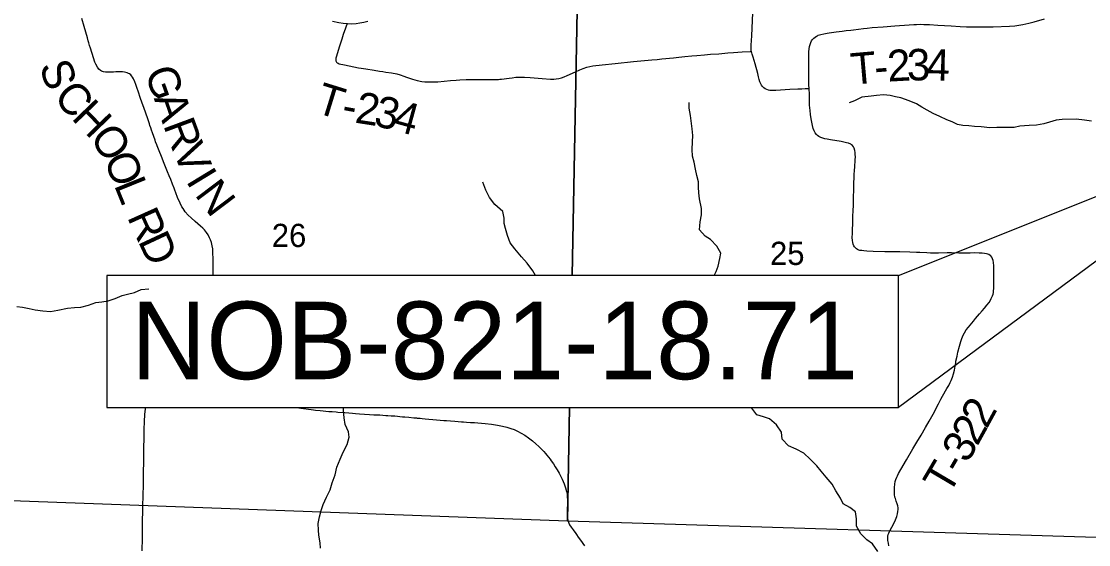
# Model space of a CAD drawing. Extents: x 0 to 34, y 0 to 22.
# Drawn here: x 3.363 to 5.288, y 16.577 to 17.521 of the extents above; entities that cross this region are included whole.
import ezdxf

# ---------------------------------------------------------------- set-up
doc = ezdxf.new("R2010")
doc.units = 0
for name, color, linetype in [('GM_X_Corporation', 7, 'Continuous'), ('GM_X_County_Road', 7, 'Continuous'), ('GM_X_Minor_River', 7, 'Continuous'), ('GM_X_Section_Text', 7, 'Continuous'), ('GM_X_State_Route', 7, 'Continuous'), ('GM_X_Township_Road', 7, 'Continuous'), ('GM_X_Township_Road_Text', 7, 'Continuous'), ('TX_P_1', 7, 'Continuous')]:
    doc.layers.add(name, color=color, linetype=linetype)

msp = doc.modelspace()

# ---------------------------------------------------------------- linework, layer by layer
at = {"layer": 'GM_X_Corporation'}
for points in [[(4.352, 16.8239), (4.3481, 16.6188), (3.3284, 16.656), (3.3465, 17.6805), (4.3675, 17.6365), (4.3565, 17.0622)], [(4.3565, 17.0622), (4.3675, 17.6365), (5.3765, 17.6099), (5.3761, 17.5925), (5.36, 16.5874), (4.3481, 16.6188), (4.352, 16.8239)]]:
    msp.add_lwpolyline(points, dxfattribs=at)
at = {"layer": 'GM_X_County_Road'}
for points in [[(3.5809, 16.5652), (3.5815, 16.5882), (3.5817, 16.6037), (3.5818, 16.6242), (3.5819, 16.6323), (3.5822, 16.6484), (3.5826, 16.6627), (3.5832, 16.6869), (3.5834, 16.7), (3.584, 16.7335), (3.5842, 16.7515), (3.5844, 16.7689), (3.5845, 16.7745), (3.5846, 16.7844), (3.585, 16.7987), (3.5856, 16.8111), (3.5861, 16.8166), (3.5867, 16.8209), (3.5874, 16.8239)], [(3.8591, 16.8239), (3.8674, 16.8227), (3.8859, 16.8204), (3.8902, 16.8199), (3.8933, 16.8195), (3.9019, 16.8186), (3.9179, 16.8171), (3.9234, 16.8166), (3.9309, 16.816), (3.934, 16.8158), (3.9463, 16.8148), (3.9537, 16.8142), (3.9605, 16.8136), (3.9655, 16.8132), (3.9729, 16.8126), (3.9907, 16.8112), (3.9987, 16.8109), (4.0099, 16.8105), (4.0148, 16.8102), (4.0204, 16.8098), (4.0241, 16.8096), (4.0303, 16.8092), (4.0347, 16.8089), (4.0365, 16.8087), (4.0507, 16.8074), (4.055, 16.807), (4.0618, 16.8065), (4.071, 16.8056), (4.0759, 16.8051), (4.0772, 16.805), (4.0809, 16.8047), (4.0821, 16.8046), (4.0858, 16.8043), (4.0914, 16.8038), (4.0982, 16.8032), (4.1055, 16.8025), (4.1251, 16.8008), (4.1299, 16.8004), (4.1373, 16.7998), (4.1447, 16.7993), (4.1509, 16.7989), (4.1571, 16.7984), (4.1608, 16.7982), (4.1657, 16.7978), (4.1732, 16.7972), (4.1806, 16.7967), (4.1862, 16.7963), (4.1998, 16.7952), (4.2109, 16.7939), (4.2219, 16.7922), (4.2311, 16.7905), (4.2389, 16.7885), (4.246, 16.7863), (4.2518, 16.7841), (4.258, 16.7813), (4.2646, 16.7779), (4.271, 16.774), (4.2776, 16.7694), (4.285, 16.7637), (4.2911, 16.7585), (4.2967, 16.7535), (4.3019, 16.7482), (4.3054, 16.7447), (4.3086, 16.7409), (4.311, 16.7381), (4.3166, 16.7307), (4.3187, 16.7277), (4.3226, 16.7223), (4.3261, 16.7172), (4.3297, 16.7114), (4.3331, 16.7055), (4.3356, 16.7005), (4.3383, 16.6949), (4.3419, 16.6863), (4.3447, 16.6788), (4.3464, 16.6723), (4.3473, 16.6674), (4.3477, 16.6631), (4.348, 16.6569), (4.3479, 16.65), (4.3475, 16.6401), (4.3474, 16.6333), (4.3476, 16.6284), (4.3484, 16.6229), (4.3494, 16.6187), (4.3506, 16.6151), (4.3519, 16.6124), (4.3548, 16.6083), (4.3583, 16.6032), (4.363, 16.5967), (4.3644, 16.5947), (4.3676, 16.5902), (4.3716, 16.5846), (4.3788, 16.5746)]]:
    msp.add_lwpolyline(points, dxfattribs=at)
at = {"layer": 'GM_X_Minor_River'}
for points in [[(5.2936, 17.3404), (5.2807, 17.3426), (5.2655, 17.344), (5.2405, 17.3438), (5.2295, 17.3422), (5.2174, 17.3387), (5.2075, 17.3356), (5.1943, 17.3332), (5.1806, 17.3327), (5.1643, 17.3314), (5.1538, 17.3291), (5.1386, 17.329), (5.1227, 17.3292), (5.1098, 17.3287), (5.0946, 17.3305), (5.0825, 17.3308), (5.0718, 17.3322), (5.0612, 17.3329), (5.0517, 17.3347), (5.0418, 17.3392), (5.0323, 17.3429), (5.0198, 17.3489), (5.008, 17.3545), (4.997, 17.3605), (4.9874, 17.3657), (4.9779, 17.3717), (4.9646, 17.3773), (4.9494, 17.3825), (4.9399, 17.3843), (4.93, 17.3869), (4.9179, 17.3883), (4.9058, 17.3867), (4.8956, 17.3858), (4.8793, 17.3838), (4.866, 17.3776), (4.8562, 17.3737)], [(4.6124, 17.0622), (4.6161, 17.0694), (4.6199, 17.0789), (4.6228, 17.093), (4.6246, 17.1025), (4.6173, 17.1149), (4.6063, 17.127), (4.5964, 17.1334), (4.5864, 17.1447), (4.5875, 17.1591), (4.5896, 17.1716), (4.5896, 17.183), (4.5864, 17.2008), (4.5852, 17.2114), (4.5844, 17.2217), (4.5843, 17.2312), (4.5815, 17.2429), (4.5788, 17.2543), (4.5764, 17.2664), (4.5737, 17.2777), (4.5733, 17.2895), (4.5735, 17.3032), (4.5742, 17.3149), (4.573, 17.3267), (4.5718, 17.3365), (4.5698, 17.3509), (4.5674, 17.3638), (4.5673, 17.3741)], [(4.2649, 17.0958), (4.2534, 17.1101), (4.2446, 17.1214), (4.24, 17.1343), (4.2361, 17.1468), (4.2341, 17.1562), (4.2341, 17.1657), (4.2313, 17.1775), (4.2168, 17.1903), (4.2073, 17.2031), (4.2011, 17.2163), (4.1957, 17.2303)], [(4.2902, 17.0622), (4.2856, 17.0705), (4.2752, 17.0845), (4.2649, 17.0958)], [(3.3549, 17.0065), (3.3648, 17.0051), (3.3773, 17.0025), (3.388, 17.0003), (3.402, 16.9982), (3.4157, 16.9971), (3.4289, 16.9995), (3.4463, 17.0031), (3.4588, 17.0043), (3.4702, 17.0052), (3.4842, 17.0087), (3.4974, 17.0137), (3.508, 17.0146), (3.5194, 17.0162), (3.5323, 17.0205), (3.5447, 17.0259), (3.5546, 17.0286), (3.5671, 17.0317), (3.5792, 17.0371), (3.5928, 17.038)], [(3.9199, 16.6752), (3.9236, 16.6882), (3.9288, 16.7026), (3.9321, 16.7163), (3.9381, 16.7311), (3.9433, 16.7433), (3.9508, 16.7574), (3.9541, 16.7704), (3.9533, 16.7802), (3.9471, 16.7931), (3.9451, 16.8056), (3.9439, 16.8192), (3.9439, 16.8239)], [(4.9079, 16.564), (4.8983, 16.578), (4.888, 16.5855), (4.8773, 16.596), (4.8696, 16.61), (4.8692, 16.6233), (4.8676, 16.6358), (4.8577, 16.6437), (4.8451, 16.6504), (4.8405, 16.6602), (4.8324, 16.6734), (4.8255, 16.6859), (4.8148, 16.6983), (4.8056, 16.7089), (4.798, 16.7187), (4.7858, 16.7307), (4.7743, 16.7417), (4.7606, 16.7488), (4.7465, 16.7547), (4.7355, 16.7671), (4.7339, 16.7797), (4.7254, 16.7925), (4.7128, 16.8034), (4.7014, 16.8071), (4.6897, 16.8108), (4.6805, 16.8229), (4.6804, 16.8239)], [(3.9025, 16.5703), (3.902, 16.5798), (3.8993, 16.5935), (3.8988, 16.603), (3.8984, 16.6147), (3.9005, 16.6269), (3.9035, 16.6383), (3.9072, 16.6493), (3.9132, 16.6623), (3.9199, 16.6752)]]:
    msp.add_lwpolyline(points, dxfattribs=at)
at = {"layer": 'GM_X_State_Route'}
msp.add_lwpolyline([(3.924, 17.5212), (3.9355, 17.5189), (3.9435, 17.5176), (3.9504, 17.5168), (3.9514, 17.5167), (3.9588, 17.5165), (3.9668, 17.517), (3.9735, 17.5179), (3.9807, 17.5192), (3.9879, 17.5211)], dxfattribs=at)
at = {"layer": 'GM_X_Township_Road'}
for points in [[(4.6799, 17.4662), (4.6797, 17.4678), (4.6796, 17.4721), (4.6797, 17.4777), (4.6806, 17.4945), (4.6823, 17.5361), (4.683, 17.551), (4.6834, 17.5565), (4.6834, 17.5584), (4.6849, 17.5776), (4.686, 17.5923), (4.686, 17.5965), (4.6857, 17.6003), (4.6851, 17.6032), (4.6839, 17.6055), (4.6823, 17.6072), (4.6793, 17.6096), (4.6761, 17.6117), (4.67, 17.6148), (4.6547, 17.6215), (4.6458, 17.626), (4.6409, 17.6288), (4.6403, 17.6292)], [(3.7088, 17.0622), (3.7087, 17.0779), (3.7087, 17.0916), (3.7086, 17.1034), (3.7081, 17.1102), (3.7074, 17.1158), (3.7058, 17.1218), (3.7042, 17.1264), (3.7024, 17.1304), (3.6997, 17.1353), (3.6967, 17.14), (3.6932, 17.1443), (3.6902, 17.1475), (3.6862, 17.1514), (3.6767, 17.1595), (3.6693, 17.166), (3.6639, 17.1712), (3.6587, 17.1773), (3.6546, 17.1829), (3.6527, 17.186), (3.6492, 17.1926), (3.6449, 17.2029), (3.6417, 17.2116), (3.6399, 17.2163), (3.6386, 17.2198), (3.6356, 17.2272), (3.6325, 17.2353), (3.6296, 17.2422), (3.6268, 17.249), (3.6219, 17.2611), (3.6193, 17.2674), (3.6168, 17.2738), (3.6144, 17.2796), (3.6126, 17.2842), (3.6079, 17.2963), (3.6072, 17.298), (3.6052, 17.3033), (3.6041, 17.3062), (3.5994, 17.3196), (3.5979, 17.3243), (3.5964, 17.3284), (3.5949, 17.3331), (3.5939, 17.336), (3.5933, 17.3378), (3.5915, 17.343), (3.5869, 17.3566), (3.5782, 17.3818), (3.5737, 17.3948), (3.5721, 17.3994), (3.5697, 17.4065), (3.5676, 17.4117), (3.5653, 17.4168), (3.5634, 17.42), (3.5616, 17.4225), (3.5602, 17.4242), (3.5582, 17.4258), (3.5561, 17.4268), (3.554, 17.4276), (3.5492, 17.4288), (3.5456, 17.4294), (3.54, 17.4296), (3.5337, 17.4295), (3.5294, 17.4292), (3.5231, 17.4289), (3.5181, 17.429), (3.5146, 17.4288), (3.5112, 17.4294), (3.5074, 17.431), (3.5057, 17.4321), (3.503, 17.4345), (3.5006, 17.4379), (3.4975, 17.4432), (3.4957, 17.4471), (3.493, 17.4548), (3.4879, 17.4721), (3.4862, 17.4774), (3.4848, 17.4822), (3.4838, 17.4858), (3.4822, 17.4911), (3.4762, 17.5114), (3.4722, 17.5258)], [(4.7839, 17.3991), (4.7836, 17.4067), (4.7837, 17.4172), (4.7836, 17.4259), (4.7836, 17.4377), (4.7836, 17.4439), (4.7835, 17.4488), (4.7835, 17.4582), (4.7837, 17.4656), (4.7841, 17.4712), (4.7848, 17.4755), (4.7857, 17.4791), (4.7871, 17.4825), (4.7885, 17.4853), (4.7902, 17.4879), (4.7923, 17.4902), (4.7946, 17.4922), (4.7972, 17.494), (4.7988, 17.4949), (4.8005, 17.4957), (4.8052, 17.4972), (4.8106, 17.4985), (4.8168, 17.4994), (4.8204, 17.5002), (4.8327, 17.5019), (4.8438, 17.5032), (4.8511, 17.5041), (4.8592, 17.5051), (4.8641, 17.5057), (4.8819, 17.5079), (4.8887, 17.5086), (4.8974, 17.5094), (4.9178, 17.511), (4.9383, 17.5125), (4.9643, 17.5146), (4.9729, 17.5152), (4.9779, 17.5153), (4.9853, 17.5154), (4.9909, 17.5153), (5.0014, 17.515), (5.0163, 17.5141), (5.0281, 17.5133), (5.0405, 17.5125), (5.0566, 17.5114), (5.0678, 17.511), (5.0771, 17.5107), (5.0888, 17.5106), (5.0975, 17.5107), (5.1159, 17.511), (5.1452, 17.512), (5.155, 17.5128), (5.1624, 17.5138), (5.1697, 17.5151), (5.18, 17.5174), (5.1901, 17.5201), (5.2086, 17.5255)], [(3.9504, 17.5168), (3.948, 17.51), (3.9474, 17.5082), (3.9436, 17.4971), (3.9409, 17.4888), (3.9362, 17.474), (3.9313, 17.4579), (3.9304, 17.4542), (3.9301, 17.4518), (3.9304, 17.4494), (3.9315, 17.4472), (3.9327, 17.4459), (3.9343, 17.445), (3.936, 17.4443), (3.9457, 17.4423), (3.9711, 17.4371), (3.9759, 17.4362), (3.9844, 17.4348), (3.9991, 17.4327), (4.0089, 17.4311), (4.015, 17.4302), (4.0205, 17.4293), (4.0309, 17.4276), (4.04, 17.4258), (4.046, 17.4242), (4.0531, 17.422), (4.0577, 17.4203), (4.0688, 17.4162), (4.0771, 17.4139), (4.0851, 17.4124), (4.0906, 17.4118), (4.0962, 17.4115), (4.1042, 17.4115), (4.1141, 17.4119), (4.1369, 17.4138), (4.1474, 17.4148), (4.1542, 17.4153), (4.1653, 17.4159), (4.174, 17.416), (4.1845, 17.4159), (4.2012, 17.4156), (4.2141, 17.4157), (4.2239, 17.4161), (4.2263, 17.4163), (4.2288, 17.4165), (4.2337, 17.417), (4.2379, 17.4175), (4.2428, 17.4182), (4.2483, 17.4191), (4.2551, 17.4198), (4.2631, 17.4202), (4.2706, 17.4202), (4.2805, 17.4196), (4.3022, 17.4177), (4.3177, 17.4167), (4.3233, 17.4167), (4.3276, 17.417), (4.3325, 17.4177), (4.3373, 17.4188), (4.3421, 17.4204), (4.3478, 17.4228), (4.3623, 17.4299), (4.3702, 17.4334), (4.3766, 17.4359), (4.3831, 17.4379), (4.3886, 17.4392), (4.3941, 17.4402), (4.4107, 17.4424), (4.4342, 17.4449), (4.467, 17.448), (4.5003, 17.4512), (4.5096, 17.4521), (4.5182, 17.4529), (4.5391, 17.4551), (4.549, 17.4561), (4.5595, 17.4572), (4.5725, 17.4586), (4.5817, 17.4593), (4.5953, 17.4605), (4.6059, 17.4613), (4.6213, 17.4624), (4.6374, 17.4637), (4.6473, 17.4646), (4.6634, 17.4658), (4.6774, 17.4661), (4.6799, 17.4662)], [(4.7839, 17.3991), (4.7769, 17.3987), (4.7708, 17.3986), (4.7638, 17.3983), (4.7489, 17.3975), (4.7241, 17.3959), (4.7179, 17.3958), (4.713, 17.3962), (4.7106, 17.3968), (4.7076, 17.3978), (4.7049, 17.3992), (4.7024, 17.401), (4.7, 17.4031), (4.698, 17.4054), (4.6966, 17.408), (4.6952, 17.4116), (4.6941, 17.4157), (4.6929, 17.4207), (4.6914, 17.4266), (4.6869, 17.444), (4.685, 17.4499), (4.6829, 17.4559), (4.6812, 17.4615), (4.6799, 17.4662)], [(4.9279, 16.5744), (4.9269, 16.5792), (4.9262, 16.5842), (4.926, 16.5879), (4.9262, 16.5916), (4.9268, 16.5946), (4.9278, 16.5975), (4.9296, 16.6014), (4.9331, 16.6079), (4.9367, 16.6149), (4.9398, 16.6216), (4.9421, 16.6274), (4.9435, 16.6321), (4.9442, 16.6364), (4.9444, 16.6401), (4.9443, 16.6431), (4.9437, 16.6468), (4.9428, 16.6503), (4.9412, 16.655), (4.9395, 16.6596), (4.9387, 16.6625), (4.9381, 16.6668), (4.9378, 16.6724), (4.938, 16.6798), (4.9385, 16.6854), (4.9394, 16.6903), (4.9406, 16.6944), (4.9423, 16.6984), (4.9433, 16.7006), (4.9455, 16.7051), (4.9493, 16.7122), (4.9595, 16.7299), (4.9709, 16.7492), (4.9783, 16.7614), (4.986, 16.7741), (4.9942, 16.7879), (5.0006, 16.7991), (5.0078, 16.8122), (5.0171, 16.8304), (5.0217, 16.8392), (5.0247, 16.8446), (5.0326, 16.8586), (5.0357, 16.864), (5.0383, 16.8689), (5.0401, 16.8728), (5.0425, 16.8786), (5.0443, 16.8845), (5.046, 16.8911), (5.0473, 16.8984), (5.0484, 16.9044), (5.0489, 16.9075), (5.0509, 16.9165), (5.0525, 16.9238), (5.0551, 16.9345), (5.0574, 16.9429), (5.0594, 16.9487), (5.0618, 16.9543), (5.0642, 16.9587), (5.0675, 16.9639), (5.0712, 16.9688), (5.0803, 16.9798), (5.0843, 16.9846), (5.088, 16.9888), (5.0916, 16.9931), (5.0964, 16.9987), (5.1005, 17.0034), (5.1048, 17.0087), (5.1085, 17.0137), (5.1111, 17.0179), (5.1125, 17.0207), (5.1145, 17.0252), (5.1157, 17.0287), (5.1164, 17.0318), (5.1167, 17.0342), (5.117, 17.0391), (5.1172, 17.0484), (5.117, 17.055), (5.117, 17.0596), (5.1173, 17.0689), (5.1171, 17.0795), (5.1166, 17.0857), (5.1159, 17.0894), (5.1149, 17.0923), (5.1135, 17.0951), (5.1116, 17.0975), (5.1107, 17.0983), (5.108, 17.1), (5.1063, 17.1007), (5.104, 17.1014), (5.1004, 17.1021), (5.096, 17.1024), (5.091, 17.1026), (5.0824, 17.1028), (5.0743, 17.1027), (5.0657, 17.1027), (5.0582, 17.1027), (5.0539, 17.1027), (5.0408, 17.1028), (5.0327, 17.1028), (5.0172, 17.1026), (5.011, 17.1026), (5.003, 17.1027), (4.9962, 17.1029), (4.9839, 17.1034), (4.9777, 17.1037), (4.9654, 17.1043), (4.9474, 17.1048), (4.9306, 17.1051), (4.9207, 17.1051), (4.8996, 17.1054), (4.8878, 17.106), (4.8828, 17.1064), (4.879, 17.107), (4.8755, 17.1075), (4.8737, 17.108), (4.8715, 17.109), (4.8694, 17.1103), (4.8675, 17.112), (4.866, 17.1139), (4.8647, 17.116), (4.8635, 17.1189), (4.8627, 17.1219), (4.8621, 17.1256), (4.8619, 17.1305), (4.862, 17.1379), (4.8624, 17.146), (4.8627, 17.1547), (4.8631, 17.1696), (4.8634, 17.1783), (4.8638, 17.1894), (4.8642, 17.2006), (4.8643, 17.2055), (4.8645, 17.2148), (4.8649, 17.2303), (4.8652, 17.2372), (4.8654, 17.2415), (4.8655, 17.244), (4.8659, 17.2521), (4.8663, 17.2576), (4.8673, 17.2707), (4.8674, 17.2763), (4.8673, 17.2807), (4.8671, 17.2842), (4.8666, 17.2879), (4.8653, 17.2917), (4.8642, 17.2941), (4.8622, 17.2968), (4.8607, 17.2981), (4.8591, 17.2991), (4.8548, 17.3007), (4.8512, 17.3016), (4.8464, 17.3028), (4.8415, 17.3037), (4.8225, 17.3069), (4.8163, 17.308), (4.8121, 17.3088), (4.8067, 17.3103), (4.805, 17.311), (4.8012, 17.313), (4.7988, 17.315), (4.797, 17.3167), (4.7948, 17.3197), (4.7928, 17.3235), (4.7914, 17.3277), (4.79, 17.3331), (4.7877, 17.3447), (4.7864, 17.3527), (4.7856, 17.3601), (4.7849, 17.3693), (4.7846, 17.3762), (4.7844, 17.3824), (4.7844, 17.3891), (4.7839, 17.3991)]]:
    msp.add_lwpolyline(points, dxfattribs=at)
at = {"layer": 'TX_P_1'}
for points in [[(4.9455, 17.0622), (5.6445, 17.3419), (4.9455, 16.8239)], [(3.517, 16.8239), (4.9455, 16.8239), (4.9455, 17.0622), (3.517, 17.0622)]]:
    msp.add_lwpolyline(points, close=True, dxfattribs=at)

# ---------------------------------------------------------------- texts
at = {"layer": 'GM_X_Section_Text'}
for s, p in [('26', (3.8147, 17.1136)), ('25', (4.7134, 17.0812))]:
    msp.add_text(s, height=0.04186, rotation=0, dxfattribs=at).set_placement(p)
at = {"layer": 'GM_X_Township_Road_Text'}
for s, rotation, p in [('T', 5.0014, (4.8612, 17.4063)), ('2', 3.1501, (4.9263, 17.4119)), ('3', 1.0981, (4.9607, 17.4138)), ('4', 358.4854, (4.995, 17.4144)), ('S', 288.4034, (3.3949, 17.4406)), ('G', 289.6261, (3.5848, 17.4291)), ('-', 4.5167, (4.9034, 17.41)), ('C', 310.919, (3.419, 17.3832)), ('T', 342.8045, (3.8907, 17.357)), ('2', 351.1405, (3.9631, 17.3382)), ('3', 346.9685, (3.9966, 17.333)), ('H', 313.977, (3.4518, 17.3455)), ('A', 289.1549, (3.6016, 17.3821)), ('-', 349.6776, (3.9386, 17.3426)), ('4', 344.6232, (4.0301, 17.3253)), ('R', 290.3778, (3.6184, 17.3336)), ('O', 303.7143, (3.4849, 17.3116)), ('V', 292.4102, (3.6355, 17.2878)), ('O', 291.2907, (3.5111, 17.2729)), ('I', 301.3208, (3.6589, 17.233)), ('L', 292.0099, (3.5296, 17.2256)), ('N', 307.0848, (3.6745, 17.2079)), ('R', 294.1579, (3.5532, 17.1679)), ('D', 295.0313, (3.5727, 17.1245)), ('2', 61.4068, (5.1044, 16.7839)), ('2', 61.039, (5.0873, 16.7529)), ('3', 60.3849, (5.0696, 16.7219)), ('T', 59.4673, (5.0358, 16.6643)), ('-', 59.7968, (5.0576, 16.7012))]:
    msp.add_text(s, height=0.0568, rotation=rotation, dxfattribs=at).set_placement(p)
at = {"layer": 'TX_P_1'}
msp.add_text('NOB-821-18.71', height=0.14, dxfattribs=at).set_placement((3.5613, 16.8751))

doc.saveas('drawing.dxf')
